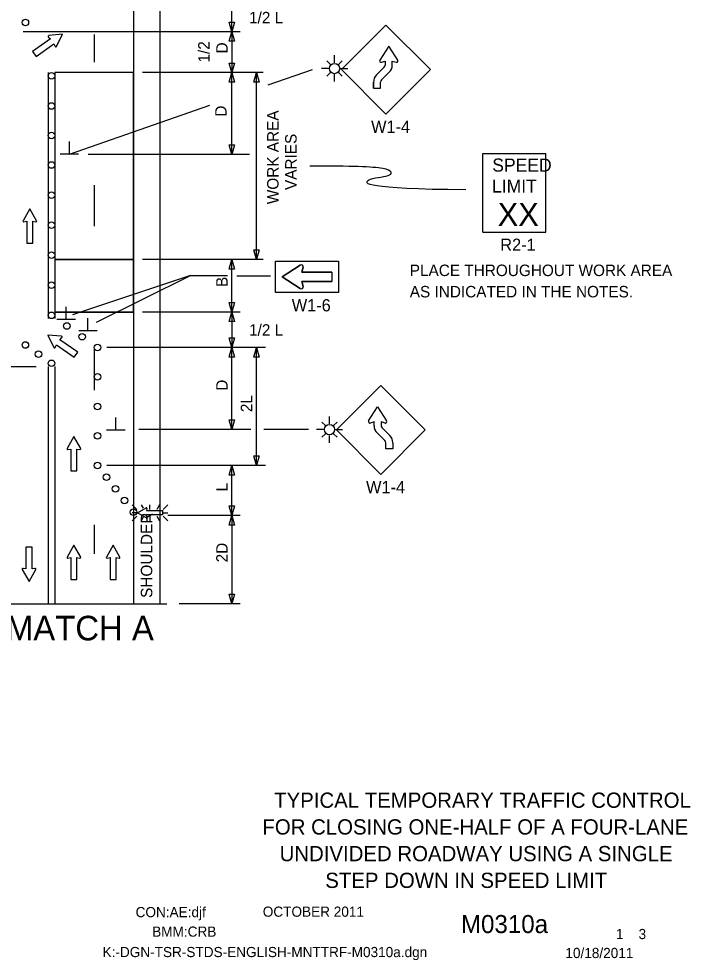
# Model space of a CAD drawing. Extents: x 16473 to 19504, y 4850 to 6919.
# Drawn here: x 17019 to 17429, y 5932 to 6506 of the extents above; entities that cross this region are included whole.
import ezdxf

# ---------------------------------------------------------------- set-up
doc = ezdxf.new("R2010")
doc.units = 0
for name, color, linetype in [('ALI_LEGAL_EX', 7, 'Continuous'), ('BORDER_SIGNAL_WO', 7, 'Continuous'), ('MT_SCRATCH_LEVEL_A', 7, 'Continuous'), ('MT_SCRATCH_LEVEL_E', 7, 'Continuous'), ('PAVT_EDGE_EX', 7, 'Continuous'), ('TRAFFIC_SIGNS_PR', 7, 'Continuous'), ('TYPICAL_TEXT_DIMEN_PR', 7, 'Continuous')]:
    doc.layers.add(name, color=color, linetype=linetype)

msp = doc.modelspace()

# ---------------------------------------------------------------- linework, layer by layer
at = {"layer": 'ALI_LEGAL_EX'}
for points in [[(17065.43, 6496.59), (17065.43, 6479.69)], [(17065.43, 6404.69), (17065.43, 6379.69)], [(17065.43, 6304.69), (17065.43, 6279.69)], [(17065.43, 6197.47), (17065.43, 6179.69)]]:
    msp.add_lwpolyline(points, dxfattribs=at)
at = {"layer": 'MT_SCRATCH_LEVEL_A'}
for p, q in [((17089.43, 6473.35), (17041.43, 6473.35)), ((17089.43, 6473.35), (17041.43, 6473.35)), ((17041.43, 6473.35), (17041.43, 6359.35)), ((17089.43, 6359.35), (17089.43, 6473.35)), ((17041.43, 6437.35), (17041.43, 6327.29)), ((17089.43, 6437.35), (17089.43, 6327.29)), ((17089.43, 6359.35), (17041.43, 6359.35)), ((17041.43, 6359.35), (17089.43, 6359.35)), ((17089.43, 6359.35), (17041.43, 6359.35)), ((17041.43, 6359.35), (17041.43, 6327.29)), ((17089.43, 6327.29), (17089.43, 6359.35)), ((17089.43, 6327.29), (17041.43, 6327.29)), ((17041.43, 6327.29), (17089.43, 6327.29))]:
    msp.add_line(p, q, dxfattribs=at)
at = {"layer": 'MT_SCRATCH_LEVEL_E'}
for p, q in [((17046, 6496.78), (17037.71, 6496)), ((17046, 6496.78), (17037.71, 6496)), ((17042.44, 6489.23), (17046, 6496.78)), ((17042.44, 6489.23), (17046, 6496.78)), ((17038.7, 6493.94), (17027.83, 6486.35)), ((17038.7, 6493.94), (17027.83, 6486.35)), ((17029.97, 6483.28), (17040.84, 6490.87)), ((17029.97, 6483.28), (17040.84, 6490.87)), ((17037.42, 6495.21), (17038.7, 6493.94)), ((17037.42, 6495.21), (17038.7, 6493.94)), ((17040.84, 6490.87), (17041.6, 6489.23)), ((17040.84, 6490.87), (17041.6, 6489.23)), ((17027.83, 6486.35), (17029.97, 6483.28)), ((17027.83, 6486.35), (17029.97, 6483.28)), ((17026.14, 6390.28), (17022.03, 6383.03)), ((17026.14, 6390.28), (17022.03, 6383.03)), ((17030.28, 6383.03), (17026.14, 6390.28)), ((17030.28, 6383.03), (17026.14, 6390.28)), ((17022.51, 6382.35), (17024.29, 6382.67)), ((17022.51, 6382.35), (17024.29, 6382.67)), ((17024.29, 6382.67), (17024.29, 6369.41)), ((17024.29, 6382.67), (17024.29, 6369.41)), ((17028.03, 6369.41), (17028.03, 6382.67)), ((17028.03, 6382.67), (17029.81, 6382.35)), ((17028.03, 6369.41), (17028.03, 6382.67)), ((17028.03, 6382.67), (17029.81, 6382.35)), ((17024.29, 6369.41), (17028.03, 6369.41)), ((17024.29, 6369.41), (17028.03, 6369.41)), ((17037.17, 6313.23), (17040.76, 6305.72)), ((17045.48, 6312.49), (17037.17, 6313.23)), ((17037.17, 6313.23), (17040.76, 6305.72)), ((17045.48, 6312.49), (17037.17, 6313.23)), ((17041.59, 6305.72), (17042.35, 6307.36)), ((17041.59, 6305.72), (17042.35, 6307.36)), ((17042.35, 6307.36), (17053.22, 6299.77)), ((17042.35, 6307.36), (17053.22, 6299.77)), ((17044.49, 6310.43), (17045.77, 6311.7)), ((17044.49, 6310.43), (17045.77, 6311.7)), ((17055.36, 6302.84), (17044.49, 6310.43)), ((17055.36, 6302.84), (17044.49, 6310.43)), ((17053.22, 6299.77), (17055.36, 6302.84)), ((17053.22, 6299.77), (17055.36, 6302.84)), ((17053.03, 6251.28), (17048.92, 6244.04)), ((17053.03, 6251.28), (17048.92, 6244.04)), ((17057.17, 6244.04), (17053.03, 6251.28)), ((17057.17, 6244.04), (17053.03, 6251.28)), ((17049.4, 6243.36), (17051.17, 6243.67)), ((17049.4, 6243.36), (17051.17, 6243.67)), ((17051.17, 6243.67), (17051.17, 6230.42)), ((17051.17, 6243.67), (17051.17, 6230.42)), ((17054.92, 6230.42), (17054.92, 6243.67)), ((17054.92, 6243.67), (17056.69, 6243.36)), ((17054.92, 6230.42), (17054.92, 6243.67)), ((17054.92, 6243.67), (17056.69, 6243.36)), ((17051.17, 6230.42), (17054.92, 6230.42)), ((17051.17, 6230.42), (17054.92, 6230.42)), ((17027.53, 6183.78), (17023.79, 6183.78)), ((17023.79, 6183.78), (17023.79, 6170.52)), ((17027.53, 6183.78), (17023.79, 6183.78)), ((17023.79, 6183.78), (17023.79, 6170.52)), ((17027.53, 6170.52), (17027.53, 6183.78)), ((17027.53, 6170.52), (17027.53, 6183.78)), ((17053.03, 6185.06), (17048.92, 6177.82)), ((17053.03, 6185.06), (17048.92, 6177.82)), ((17057.17, 6177.82), (17053.03, 6185.06)), ((17057.17, 6177.82), (17053.03, 6185.06)), ((17076.95, 6185.06), (17072.84, 6177.82)), ((17076.95, 6185.06), (17072.84, 6177.82)), ((17081.1, 6177.82), (17076.95, 6185.06)), ((17081.1, 6177.82), (17076.95, 6185.06)), ((17049.4, 6177.14), (17051.17, 6177.45)), ((17049.4, 6177.14), (17051.17, 6177.45)), ((17051.17, 6177.45), (17051.17, 6164.2)), ((17051.17, 6177.45), (17051.17, 6164.2)), ((17054.92, 6164.2), (17054.92, 6177.45)), ((17054.92, 6177.45), (17056.69, 6177.14)), ((17054.92, 6164.2), (17054.92, 6177.45)), ((17054.92, 6177.45), (17056.69, 6177.14)), ((17073.32, 6177.14), (17075.1, 6177.45)), ((17073.32, 6177.14), (17075.1, 6177.45)), ((17075.1, 6177.45), (17075.1, 6164.2)), ((17075.1, 6177.45), (17075.1, 6164.2)), ((17078.84, 6164.2), (17078.84, 6177.45)), ((17078.84, 6177.45), (17080.62, 6177.14)), ((17078.84, 6164.2), (17078.84, 6177.45)), ((17078.84, 6177.45), (17080.62, 6177.14)), ((17021.53, 6170.15), (17025.68, 6162.91)), ((17021.53, 6170.15), (17025.68, 6162.91)), ((17023.79, 6170.52), (17022.01, 6170.84)), ((17023.79, 6170.52), (17022.01, 6170.84)), ((17025.68, 6162.91), (17029.79, 6170.15)), ((17025.68, 6162.91), (17029.79, 6170.15)), ((17029.31, 6170.84), (17027.53, 6170.52)), ((17029.31, 6170.84), (17027.53, 6170.52)), ((17051.17, 6164.2), (17054.92, 6164.2)), ((17051.17, 6164.2), (17054.92, 6164.2)), ((17075.1, 6164.2), (17078.84, 6164.2)), ((17075.1, 6164.2), (17078.84, 6164.2))]:
    msp.add_line(p, q, dxfattribs=at)
for centre, start, end in [((17037.76, 6495.54), 95.35608, 224.89505), ((17037.76, 6495.54), 95.35608, 224.89505), ((17042.02, 6489.44), 204.96744, 334.70436), ((17042.02, 6489.44), 204.96744, 334.70436), ((17022.43, 6382.81), 150.42484, 279.96381), ((17022.43, 6382.81), 150.42484, 279.96381), ((17029.87, 6382.81), 260.03619, 29.77312), ((17029.87, 6382.81), 260.03619, 29.77312), ((17045.43, 6312.02), 315.10498, 84.84191), ((17045.43, 6312.02), 315.10498, 84.84191), ((17041.17, 6305.92), 205.49363, 335.0326), ((17041.17, 6305.92), 205.49363, 335.0326), ((17049.32, 6243.82), 150.42484, 279.96381), ((17049.32, 6243.82), 150.42484, 279.96381), ((17056.76, 6243.82), 260.03619, 29.77312), ((17056.76, 6243.82), 260.03619, 29.77312), ((17049.32, 6177.6), 150.42484, 279.96381), ((17049.32, 6177.6), 150.42484, 279.96381), ((17056.76, 6177.6), 260.03619, 29.77312), ((17056.76, 6177.6), 260.03619, 29.77312), ((17073.25, 6177.6), 150.42484, 279.96381), ((17073.25, 6177.6), 150.42484, 279.96381), ((17080.69, 6177.6), 260.03619, 29.77312), ((17080.69, 6177.6), 260.03619, 29.77312), ((17021.94, 6170.37), 80.03619, 209.77312), ((17021.94, 6170.37), 80.03619, 209.77312), ((17029.38, 6170.38), 330.42484, 99.96381), ((17029.38, 6170.38), 330.42484, 99.96381)]:
    msp.add_arc(centre, 0.463, start, end, dxfattribs=at)
at = {"layer": 'PAVT_EDGE_EX'}
for p, q in [((17089.43, 6873.99), (17089.43, 6149.2)), ((17105.43, 6873.99), (17105.43, 6149.2)), ((17037.43, 6473.35), (17037.43, 6323.29)), ((17041.43, 6437.35), (17041.43, 6323.29)), ((17037.43, 6294.02), (17037.43, 6149.2)), ((17041.43, 6294.02), (17041.43, 6149.2))]:
    msp.add_line(p, q, dxfattribs=at)
at = {"layer": 'TRAFFIC_SIGNS_PR'}
for p, q in [((17243.38, 6502.37), (17216.23, 6475.22)), ((17270.53, 6475.22), (17243.38, 6502.37)), ((17209.54, 6478.39), (17207.43, 6480.5)), ((17212.06, 6479.43), (17212.06, 6483.94)), ((17214.57, 6478.39), (17216.68, 6480.5)), ((17208.9, 6475.88), (17204.06, 6475.88)), ((17209.54, 6473.37), (17207.43, 6471.26)), ((17214.57, 6473.37), (17216.68, 6471.26)), ((17215.21, 6475.88), (17220.09, 6475.88)), ((17216.23, 6475.22), (17243.38, 6448.07)), ((17237.72, 6471.97), (17242.44, 6476.68)), ((17242.44, 6476.68), (17237.72, 6471.97)), ((17240.77, 6468.92), (17245.49, 6473.63)), ((17240.78, 6468.92), (17245.49, 6473.63)), ((17243.38, 6448.07), (17270.53, 6475.22)), ((17212.06, 6467.91), (17212.06, 6472.33)), ((17235.86, 6463.85), (17235.86, 6467.55)), ((17240.17, 6463.85), (17240.17, 6467.55)), ((17235.86, 6463.85), (17240.17, 6463.85)), ((17302.54, 6424.09), (17340.94, 6424.09)), ((17302.54, 6376.09), (17302.54, 6424.09)), ((17340.94, 6376.09), (17340.94, 6424.09)), ((17302.54, 6376.09), (17340.94, 6376.09)), ((17191.2, 6355.85), (17180.04, 6348.75)), ((17192.04, 6351.55), (17192.88, 6354.61)), ((17180.04, 6348.75), (17191.2, 6341.65)), ((17210.44, 6351.55), (17192.04, 6351.55)), ((17210.44, 6351.55), (17210.44, 6345.95)), ((17192.88, 6342.89), (17192.04, 6345.95)), ((17192.04, 6345.95), (17210.44, 6345.95)), ((17213.17, 6255.35), (17240.32, 6282.5)), ((17267.47, 6255.35), (17240.32, 6282.5)), ((17209, 6259.11), (17209, 6263.61)), ((17205.84, 6255.56), (17201.01, 6255.56)), ((17206.49, 6258.07), (17204.38, 6260.18)), ((17211.51, 6258.07), (17213.62, 6260.18)), ((17212.15, 6255.56), (17217.03, 6255.56)), ((17240.32, 6228.2), (17213.17, 6255.35)), ((17267.47, 6255.35), (17240.32, 6228.2)), ((17245.79, 6251.88), (17241.08, 6256.6)), ((17241.08, 6256.6), (17245.79, 6251.88)), ((17206.48, 6253.04), (17204.38, 6250.94)), ((17209, 6247.59), (17209, 6252)), ((17211.51, 6253.04), (17213.62, 6250.94)), ((17242.74, 6248.83), (17238.03, 6253.55)), ((17242.74, 6248.83), (17238.03, 6253.55)), ((17088.56, 6209.69), (17091.38, 6206.87)), ((17094, 6209.69), (17095.21, 6207.59)), ((17099.47, 6206.87), (17099.47, 6209.69)), ((17105.26, 6209.69), (17103.63, 6206.87)), ((17107.55, 6206.87), (17110.37, 6209.69)), ((17091.38, 6204.84), (17088.56, 6204.84)), ((17107.55, 6204.84), (17110.37, 6204.84)), ((17088.56, 6199.99), (17091.38, 6202.8)), ((17095.28, 6202.17), (17094.02, 6199.98)), ((17099.47, 6202.8), (17099.47, 6199.98)), ((17103.6, 6202.8), (17105.23, 6199.98)), ((17107.55, 6202.8), (17110.37, 6199.98))]:
    msp.add_line(p, q, dxfattribs=at)
for points in [[(17250.64, 6480.96), (17245.16, 6489.57), (17239.68, 6480.96)], [(17250.64, 6480.96), (17245.16, 6489.57), (17239.68, 6480.96)], [(17240.64, 6479.66), (17243, 6480.31), (17243, 6478.01)], [(17240.64, 6479.66), (17241.47, 6479.89), (17243, 6480.31), (17243, 6478.01)], [(17247.31, 6477.94), (17247.32, 6480.31), (17249.68, 6479.66)], [(17235.86, 6467.55), (17235.86, 6463.85), (17240.17, 6463.85), (17240.17, 6467.55)], [(17191.2, 6341.65), (17180.04, 6348.75), (17191.2, 6355.85)], [(17192.88, 6354.61), (17192.04, 6351.55), (17210.44, 6351.55), (17210.44, 6345.95), (17192.04, 6345.95), (17192.88, 6342.89)], [(17232.87, 6260.87), (17238.36, 6269.48), (17243.84, 6260.87)], [(17232.87, 6260.87), (17238.36, 6269.48), (17243.84, 6260.87)], [(17236.2, 6257.86), (17236.2, 6260.22), (17233.83, 6259.58)], [(17236.2, 6257.86), (17236.2, 6260.22), (17233.83, 6259.58)], [(17242.88, 6259.58), (17240.51, 6260.22), (17240.52, 6257.93)], [(17242.88, 6259.57), (17242.04, 6259.8), (17240.51, 6260.22), (17240.52, 6257.93)], [(17247.66, 6247.46), (17247.66, 6243.76), (17243.34, 6243.76), (17243.34, 6247.46)], [(17097.14, 6201.82), (17091.83, 6204.84), (17097.14, 6207.88)], [(17097.64, 6207.52), (17097.41, 6206.22), (17107.13, 6206.22), (17107.13, 6203.48), (17097.41, 6203.48), (17097.64, 6202.17)]]:
    msp.add_lwpolyline(points, dxfattribs=at)
msp.add_lwpolyline([(17214.44, 6339.15), (17176.04, 6339.15), (17176.04, 6358.35), (17214.44, 6358.35)], close=True, dxfattribs=at)
for centre, radius in [((17023.43, 6503.94), 2), ((17212.06, 6475.88), 3.15), ((17039.43, 6471.35), 2), ((17039.43, 6453.01), 2), ((17039.43, 6435.01), 2), ((17039.43, 6417.01), 2), ((17039.43, 6398.66), 2), ((17039.43, 6380.32), 2), ((17039.43, 6361.98), 2), ((17039.43, 6343.63), 2), ((17039.43, 6325.29), 2), ((17048.77, 6318.77), 2), ((17058.11, 6312.24), 2), ((17023.43, 6307.19), 2), ((17067.46, 6305.72), 2), ((17031.43, 6301.6), 2), ((17039.43, 6296.02), 2), ((17067.46, 6287.72), 2), ((17067.46, 6269.72), 2), ((17209, 6255.56), 3.15), ((17067.46, 6251.72), 2), ((17067.46, 6233.72), 2), ((17072.95, 6226.58), 2), ((17078.45, 6219.46), 2), ((17083.95, 6212.33), 2), ((17089.44, 6205.2), 2)]:
    msp.add_circle(centre, radius, dxfattribs=at)
for centre, radius, start, end in [((17240.41, 6480.49), 0.866, 147.52881, 285.38519), ((17240.41, 6480.49), 0.864, 147.52044, 285.3986), ((17249.91, 6480.5), 0.866, 254.67989, 32.28036), ((17241.15, 6478.01), 1.85, 314.21254, 0), ((17241.15, 6478.01), 1.85, 314.2123, 0.1238), ((17241.15, 6478.01), 6.17, 314.21254, 359.38189), ((17241.15, 6478.01), 6.17, 314.76872, 359.37555), ((17242.02, 6467.55), 6.17, 134.21254, 180), ((17242.02, 6467.55), 6.17, 134.21254, 180), ((17242.02, 6467.55), 6.17, 134.21172, 180), ((17242.02, 6467.55), 1.85, 132.37199, 180), ((17242.02, 6467.55), 1.85, 134.21254, 180), ((17191.8, 6354.91), 1.12, 344.67308, 122.46963), ((17191.8, 6354.91), 1.12, 344.67308, 122.46962), ((17191.8, 6342.59), 1.12, 237.53038, 15.32692), ((17191.8, 6342.59), 1.12, 237.53038, 15.32692), ((17233.6, 6260.41), 0.866, 147.7292, 285.31719), ((17233.61, 6260.41), 0.866, 147.71964, 285.32011), ((17223.76, 6266.67), 10.8, 327.53351, 327.54311), ((17243.11, 6260.41), 0.866, 254.61481, 32.47119), ((17236.69, 6249.16), 10.8, 105.31922, 105.32004), ((17242.37, 6257.92), 6.17, 180.61811, 225.78746), ((17242.37, 6257.93), 6.17, 180.62445, 225.23128), ((17242.37, 6257.93), 1.85, 179.8762, 225.7877), ((17242.37, 6257.92), 1.85, 180, 225.78746), ((17241.49, 6247.46), 6.17, 0, 45.78828), ((17241.49, 6247.46), 1.85, 0, 47.62801), ((17097.3, 6207.58), 0.341, 350.04067, 118.51671), ((17097.31, 6202.12), 0.341, 241.10835, 9.26922)]:
    msp.add_arc(centre, radius, start, end, dxfattribs=at)
at = {"layer": 'TYPICAL_TEXT_DIMEN_PR'}
for p, q in [((17149.43, 6498.35), (17149.43, 6517.11)), ((17149.43, 6498.35), (17147.86, 6504.22)), ((17147.86, 6504.22), (17149.43, 6504.22)), ((17149.43, 6504.22), (17151, 6504.22)), ((17151, 6504.22), (17149.43, 6498.35)), ((17154.43, 6498.35), (17022.11, 6498.35)), ((17147.86, 6492.49), (17149.43, 6498.35)), ((17149.43, 6498.35), (17151, 6492.49)), ((17149.43, 6498.35), (17149.43, 6473.35)), ((17149.43, 6492.49), (17147.86, 6492.49)), ((17151, 6492.49), (17149.43, 6492.49)), ((17149.43, 6473.35), (17147.86, 6479.22)), ((17147.86, 6479.22), (17149.43, 6479.22)), ((17149.43, 6479.22), (17151, 6479.22)), ((17151, 6479.22), (17149.43, 6473.35)), ((17168.56, 6473.35), (17094.94, 6473.35)), ((17147.86, 6467.49), (17149.43, 6473.35)), ((17149.43, 6423.35), (17149.43, 6473.35)), ((17149.43, 6473.35), (17151, 6467.49)), ((17162.86, 6467.49), (17164.43, 6473.35)), ((17164.43, 6359.35), (17164.43, 6473.35)), ((17164.43, 6473.35), (17166, 6467.49)), ((17171.56, 6465.95), (17198.58, 6475.37)), ((17149.43, 6467.49), (17147.86, 6467.49)), ((17151, 6467.49), (17149.43, 6467.49)), ((17164.43, 6467.49), (17162.86, 6467.49)), ((17166, 6467.49), (17164.43, 6467.49)), ((17050.28, 6423.65), (17135.96, 6453.53)), ((17050.28, 6423.65), (17050.28, 6431.44)), ((17149.43, 6423.35), (17147.86, 6429.22)), ((17147.86, 6429.22), (17149.43, 6429.22)), ((17149.43, 6429.22), (17151, 6429.22)), ((17151, 6429.22), (17149.43, 6423.35)), ((17055.9, 6423.65), (17044.65, 6423.65)), ((17160.28, 6423.35), (17061.75, 6423.35)), ((17164.43, 6359.35), (17162.86, 6365.21)), ((17162.86, 6365.21), (17164.43, 6365.21)), ((17164.43, 6365.21), (17166, 6365.21)), ((17166, 6365.21), (17164.43, 6359.35)), ((17168.56, 6359.35), (17094.94, 6359.35)), ((17147.86, 6353.49), (17149.43, 6359.35)), ((17149.43, 6327.29), (17149.43, 6359.35)), ((17149.43, 6359.35), (17151, 6353.49)), ((17149.43, 6353.49), (17147.86, 6353.49)), ((17151, 6353.49), (17149.43, 6353.49)), ((17124.13, 6349.55), (17052.22, 6325.63)), ((17066.74, 6321.03), (17124.13, 6349.55)), ((17124.13, 6349.55), (17146.71, 6349.55)), ((17152.53, 6349.46), (17173.03, 6349.46)), ((17048.33, 6322.74), (17048.33, 6330.52)), ((17149.43, 6327.29), (17147.86, 6333.15)), ((17147.86, 6333.15), (17149.43, 6333.15)), ((17149.43, 6333.15), (17151, 6333.15)), ((17151, 6333.15), (17149.43, 6327.29)), ((17061.59, 6315.87), (17061.59, 6323.65)), ((17154.43, 6327.29), (17094.94, 6327.29)), ((17147.86, 6321.43), (17149.43, 6327.29)), ((17149.43, 6327.29), (17149.43, 6305.72)), ((17149.43, 6327.29), (17151, 6321.43)), ((17053.96, 6322.74), (17042.71, 6322.74)), ((17149.43, 6321.43), (17147.86, 6321.43)), ((17151, 6321.43), (17149.43, 6321.43)), ((17067.21, 6315.87), (17055.96, 6315.87)), ((17149.43, 6305.72), (17147.86, 6311.58)), ((17147.86, 6311.58), (17149.43, 6311.58)), ((17149.43, 6311.58), (17151, 6311.58)), ((17151, 6311.58), (17149.43, 6305.72)), ((17154.43, 6305.72), (17073.2, 6305.72)), ((17154.43, 6305.72), (17073.2, 6305.72)), ((17169.86, 6305.72), (17073.2, 6305.72)), ((17147.86, 6299.86), (17149.43, 6305.72)), ((17149.43, 6255.72), (17149.43, 6305.72)), ((17149.43, 6305.72), (17151, 6299.86)), ((17162.86, 6299.86), (17164.43, 6305.72)), ((17164.43, 6233.72), (17164.43, 6305.72)), ((17164.43, 6305.72), (17166, 6299.86)), ((17149.43, 6299.86), (17147.86, 6299.86)), ((17151, 6299.86), (17149.43, 6299.86)), ((17164.43, 6299.86), (17162.86, 6299.86)), ((17166, 6299.86), (17164.43, 6299.86)), ((16924.43, 6294.02), (17029.97, 6294.02)), ((17078.59, 6255.17), (17078.59, 6262.96)), ((17149.43, 6255.72), (17147.86, 6261.58)), ((17147.86, 6261.58), (17149.43, 6261.58)), ((17149.43, 6261.58), (17151, 6261.58)), ((17151, 6261.58), (17149.43, 6255.72)), ((17084.22, 6255.17), (17072.97, 6255.17)), ((17161.07, 6255.72), (17092.61, 6255.72)), ((17196.26, 6255.72), (17168.98, 6255.72)), ((17164.43, 6233.72), (17162.86, 6239.58)), ((17162.86, 6239.58), (17164.43, 6239.58)), ((17164.43, 6239.58), (17166, 6239.58)), ((17166, 6239.58), (17164.43, 6233.72)), ((17169.86, 6233.72), (17073.2, 6233.72)), ((17147.86, 6227.85), (17149.43, 6233.72)), ((17149.43, 6203.2), (17149.43, 6233.72)), ((17149.43, 6233.72), (17151, 6227.85)), ((17149.43, 6227.85), (17147.86, 6227.85)), ((17151, 6227.85), (17149.43, 6227.85)), ((17149.43, 6203.2), (17147.86, 6209.07)), ((17147.86, 6209.07), (17149.43, 6209.07)), ((17149.43, 6209.07), (17151, 6209.07)), ((17151, 6209.07), (17149.43, 6203.2)), ((17154.43, 6203.2), (17110.45, 6203.2)), ((17147.86, 6197.34), (17149.43, 6203.2)), ((17149.43, 6203.2), (17149.43, 6149.2)), ((17149.43, 6203.2), (17151, 6197.34)), ((17149.43, 6197.34), (17147.86, 6197.34)), ((17151, 6197.34), (17149.43, 6197.34)), ((17149.43, 6149.2), (17147.86, 6155.07)), ((17147.86, 6155.07), (17149.43, 6155.07)), ((17149.43, 6155.07), (17151, 6155.07)), ((17151, 6155.07), (17149.43, 6149.2)), ((16969.13, 6149.2), (17109.73, 6149.2)), ((17154.43, 6149.2), (17117.3, 6149.2))]:
    msp.add_line(p, q, dxfattribs=at)
msp.add_open_spline([(17292.26, 6401.88), (17229.81, 6402.24), (17229.81, 6409.49), (17247.7, 6409.49), (17247.7, 6415.76), (17222.69, 6416.28), (17196.97, 6416.33)], degree=3, dxfattribs=at)

# ---------------------------------------------------------------- texts
at = {"layer": 'BORDER_SIGNAL_WO'}
for s, height, p in [('TYPICAL TEMPORARY TRAFFIC CONTROL', 9.3, (17175.21, 6024.8)), ('FOR CLOSING ONE-HALF OF A FOUR-LANE', 9.3, (17168.06, 6008.5)), ('UNDIVIDED ROADWAY USING A SINGLE', 9.3, (17178.56, 5992.2)), ('STEP DOWN IN SPEED LIMIT', 9.3, (17206.42, 5975.9)), ('CON:AE:djf', 6.2, (17090.69, 5958.06)), ('    OCTOBER 2011    ', 6.2, (17159.08, 5958.34)), ('    M0310a   ', 11, (17272.86, 5948.38)), ('BMM:CRB   ', 6.2, (17100.81, 5946.17)), (' 1    3 ', 6.2, (17381.45, 5944.7)), ('K:-DGN-TSR-STDS-ENGLISH-MNTTRF-M0310a.dgn        ', 6.2, (17070.55, 5933.71)), ('10/18/2011    ', 6.2, (17352.93, 5933.13))]:
    msp.add_text(s, height=height, dxfattribs=at).set_placement(p)
at = {"layer": 'TRAFFIC_SIGNS_PR'}
for s, height, p in [('W1-4', 7.44, (17234.38, 6436.63)), ('SPEED', 8, (17308.31, 6412.96)), ('LIMIT', 8, (17308.15, 6400.16)), ('XX', 14.031, (17311.65, 6379.85)), ('R2-1', 7.44, (17313.22, 6364.65)), ('PLACE THROUGHOUT WORK AREA', 7, (17257.98, 6349.23)), ('AS INDICATED IN THE NOTES.', 7, (17257.98, 6336.23)), ('W1-6', 7.44, (17185.98, 6327.71)), ('W1-4', 7.44, (17231.32, 6216.76))]:
    msp.add_text(s, height=height, dxfattribs=at).set_placement(p)
at = {"layer": 'TYPICAL_TEXT_DIMEN_PR'}
for s, height, p in [('1/2 L', 7, (17159.9, 6503.44)), ('1/2 L', 7, (17159.9, 6312.85)), ('A MATCH A', 15, (16992.6, 6126.96))]:
    msp.add_text(s, height=height, dxfattribs=at).set_placement(p)
for s, p in [('1/2', (17135.87, 6479.5)), ('D', (17146.87, 6485.07)), ('D', (17146.24, 6446.49)), ('WORK AREA', (17177.94, 6393.09)), ('VARIES', (17188.94, 6401.74)), ('B', (17146.87, 6342.55)), ('D', (17146.87, 6279.27)), ('2L', (17161.87, 6266.22)), ('L', (17146.87, 6217.82)), ('SHOULDER', (17100.87, 6152.87)), ('2D', (17146.87, 6174.55))]:
    msp.add_text(s, height=7, rotation=90, dxfattribs=at).set_placement(p)

doc.saveas('drawing.dxf')
